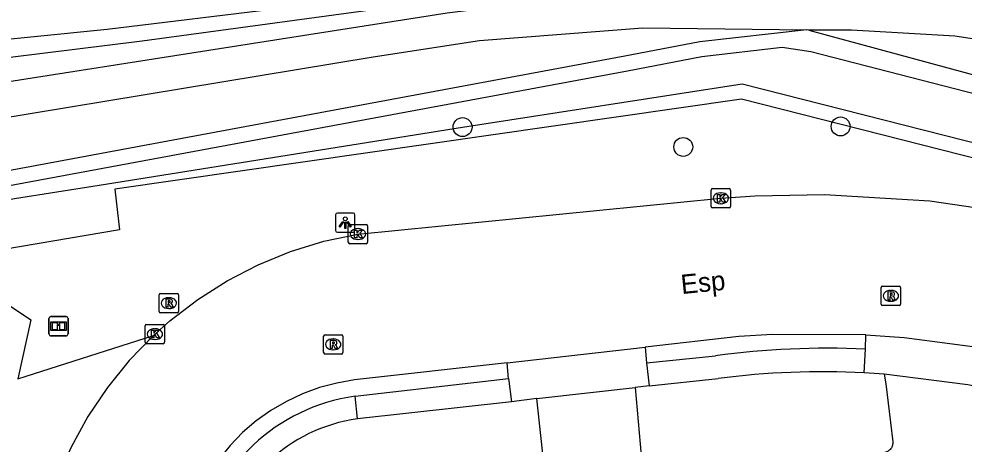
# Model space of a CAD drawing. Extents: x 161389 to 162585, y 388479 to 389761.
# Drawn here: x 162401.19 to 162450.14, y 389087.1 to 389109.12 of the extents above; entities that cross this region are included whole.
import ezdxf

# ---------------------------------------------------------------- set-up
doc = ezdxf.new("R2010")
doc.units = 0
for name, color, linetype in [('IMGEO_Boom', 7, 'Continuous'), ('IMGEO_Grasland_overig', 7, 'Continuous'), ('IMGEO_Groenvoorziening', 7, 'Continuous'), ('IMGEO_Informatiebord', 7, 'Continuous'), ('IMGEO_Kolk', 7, 'Continuous'), ('IMGEO_Lichtpunt', 7, 'Continuous'), ('IMGEO_Openbare_ruimte_label', 7, 'Continuous'), ('IMGEO_Rijbaan_lokaal_gesloten', 7, 'Continuous'), ('IMGEO_Rijbaan_lokaal_open', 7, 'Continuous'), ('IMGEO_Rioolput', 7, 'Continuous'), ('IMGEO_Voetpad_open', 7, 'Continuous'), ('IMGEO_Waterloop', 7, 'Continuous')]:
    doc.layers.add(name, color=color, linetype=linetype)

msp = doc.modelspace()

# ---------------------------------------------------------------- linework, layer by layer
at = {"layer": 'IMGEO_Boom'}
for centre in [(162424.166, 389103.514), (162443.743, 389103.548), (162435.594, 389102.487)]:
    msp.add_circle(centre, 0.489, dxfattribs=at)
at = {"layer": 'IMGEO_Grasland_overig'}
for points in [[(162443.128, 389111.815), (162441.869, 389111.714), (162423.37, 389109.414), (162387.435, 389103.792), (162386.449, 389103.86), (162385.337, 389104.032), (162384.246, 389104.303), (162383.182, 389104.67), (162382.156, 389105.13), (162381.175, 389105.68), (162380.247, 389106.316), (162379.38, 389107.032), (162377.829, 389109.083), (162376.361, 389111.024), (162369.698, 389125.495), (162363.721, 389145.826)], [(162345.171, 389069.022), (162346.529, 389070.241), (162347.773, 389071.576), (162348.632, 389072.657), (162357.656, 389083.031), (162363.851, 389089.234), (162366.896, 389092.076), (162370.937, 389095.277), (162372.4, 389096.154), (162374.82, 389097.375), (162377.339, 389098.374), (162379.935, 389099.397), (162385.624, 389101.218), (162387.811, 389101.86), (162390.049, 389102.288), (162419.529, 389107.157), (162425.043, 389108), (162433.502, 389108.658), (162441.985, 389108.557)], [(162442.099, 389108.529), (162441.985, 389108.557)], [(162490.431, 389095.003), (162489.427, 389095.363), (162466.901, 389103.815), (162460.173, 389106.152), (162454.96, 389107.42), (162449.656, 389108.217), (162444.301, 389108.537), (162442.099, 389108.529)]]:
    msp.add_lwpolyline(points, dxfattribs=at)
at = {"layer": 'IMGEO_Groenvoorziening'}
for points in [[(162378.38, 389110.682), (162379.528, 389110.312), (162380.637, 389109.275), (162382.947, 389107.385), (162384.59, 389106.646), (162386.048, 389106.318), (162393.071, 389106.318), (162399.046, 389106.934), (162407.567, 389107.981), (162426.033, 389110.496), (162442.252, 389112.986)], [(162441.985, 389108.557), (162436.446, 389107.928), (162432.566, 389107.183), (162394.86, 389100.187), (162377.318, 389096.648)], [(162442.099, 389108.529), (162463.695, 389102.686), (162488.778, 389092.794), (162488.169, 389091.372), (162487.431, 389089.647), (162462.452, 389098.908), (162438.603, 389104.956), (162406.149, 389100.295), (162406.403, 389098.189), (162400.404, 389097.175)], [(162345.423, 389058.454), (162354.094, 389069), (162374.638, 389088.034), (162399.442, 389095.107), (162401.799, 389093.537), (162401.128, 389090.478), (162408.163, 389092.728)]]:
    msp.add_lwpolyline(points, dxfattribs=at)
at = {"layer": 'IMGEO_Informatiebord'}
for p, q in [((162402.843, 389093.704), (162403.633, 389093.704)), ((162403.633, 389093.704), (162402.843, 389093.704)), ((162402.743, 389092.804), (162402.743, 389093.604)), ((162402.743, 389093.604), (162402.743, 389092.804)), ((162403.733, 389093.604), (162403.733, 389092.804)), ((162403.733, 389092.804), (162403.733, 389093.604)), ((162403.633, 389092.704), (162402.843, 389092.704)), ((162402.843, 389092.704), (162403.633, 389092.704))]:
    msp.add_line(p, q, dxfattribs=at)
for points in [[(162402.844, 389093.436), (162403.632, 389093.436), (162403.632, 389092.972), (162402.844, 389092.972), (162402.844, 389093.436)], [(162402.909, 389093.371), (162402.909, 389093.037), (162403.184, 389093.037), (162403.185, 389093.25), (162403.289, 389093.251), (162403.29, 389093.037), (162403.567, 389093.037), (162403.567, 389093.371), (162403.291, 389093.371), (162403.291, 389093.291), (162403.185, 389093.291), (162403.185, 389093.371), (162402.909, 389093.371)]]:
    msp.add_lwpolyline(points, dxfattribs=at)
for centre, start, end in [((162402.843, 389093.604), 90, 180), ((162402.843, 389093.604), 90, 180), ((162403.633, 389093.604), 0, 90), ((162403.633, 389093.604), 360, 90), ((162402.843, 389092.804), 180, 270), ((162402.843, 389092.804), 180, 270), ((162403.633, 389092.804), 270, 0), ((162403.633, 389092.804), 270, 0)]:
    msp.add_arc(centre, 0.1, start, end, dxfattribs=at)
at = {"layer": 'IMGEO_Kolk'}
for p, q in [((162437.039, 389099.401), (162437.039, 389100.253)), ((162437.114, 389100.327), (162437.966, 389100.327)), ((162437.527, 389100.107), (162437.552, 389100.107)), ((162438.04, 389100.253), (162438.04, 389099.401)), ((162437.55, 389099.547), (162437.525, 389099.547)), ((162437.966, 389099.327), (162437.114, 389099.327)), ((162418.246, 389097.55), (162418.246, 389098.402)), ((162418.321, 389098.476), (162419.173, 389098.476)), ((162418.734, 389098.256), (162418.759, 389098.256)), ((162419.247, 389098.402), (162419.247, 389097.55)), ((162418.757, 389097.696), (162418.732, 389097.696)), ((162419.173, 389097.476), (162418.321, 389097.476)), ((162407.731, 389092.369), (162407.731, 389093.221)), ((162407.806, 389093.295), (162408.658, 389093.295)), ((162408.732, 389093.221), (162408.732, 389092.369)), ((162408.219, 389093.075), (162408.244, 389093.075)), ((162408.658, 389092.295), (162407.806, 389092.295)), ((162408.242, 389092.515), (162408.217, 389092.515))]:
    msp.add_line(p, q, dxfattribs=at)
for points in [[(162437.039, 389099.401), (162437.039, 389100.253)], [(162437.114, 389100.327), (162437.966, 389100.327)], [(162437.36, 389100.027), (162437.483, 389100.027), (162437.483, 389099.876), (162437.613, 389100.027), (162437.777, 389100.027), (162437.631, 389099.876), (162437.784, 389099.627), (162437.632, 389099.627), (162437.547, 389099.791), (162437.483, 389099.724), (162437.483, 389099.627), (162437.36, 389099.627), (162437.36, 389100.027)], [(162438.04, 389100.253), (162438.04, 389099.401)], [(162437.966, 389099.327), (162437.114, 389099.327)], [(162418.246, 389097.55), (162418.246, 389098.402)], [(162418.321, 389098.476), (162419.173, 389098.476)], [(162418.567, 389098.176), (162418.69, 389098.176), (162418.69, 389098.025), (162418.82, 389098.176), (162418.984, 389098.176), (162418.838, 389098.025), (162418.991, 389097.776), (162418.839, 389097.776), (162418.754, 389097.94), (162418.69, 389097.873), (162418.69, 389097.776), (162418.567, 389097.776), (162418.567, 389098.176)], [(162419.247, 389098.402), (162419.247, 389097.55)], [(162419.173, 389097.476), (162418.321, 389097.476)], [(162407.731, 389092.369), (162407.731, 389093.221)], [(162407.806, 389093.295), (162408.658, 389093.295)], [(162408.732, 389093.221), (162408.732, 389092.369)], [(162408.052, 389092.995), (162408.175, 389092.995), (162408.175, 389092.844), (162408.305, 389092.995), (162408.469, 389092.995), (162408.323, 389092.844), (162408.476, 389092.595), (162408.324, 389092.595), (162408.239, 389092.759), (162408.175, 389092.692), (162408.175, 389092.595), (162408.052, 389092.595), (162408.052, 389092.995)], [(162408.658, 389092.295), (162407.806, 389092.295)]]:
    msp.add_lwpolyline(points, dxfattribs=at)
for centre, start, end in [((162437.116, 389100.251), 91.552, 178.448), ((162437.116, 389100.251), 91.552, 178.448), ((162437.964, 389100.251), 1.552, 88.448), ((162437.964, 389100.251), 1.552, 88.448), ((162437.116, 389099.403), 181.552, 268.448), ((162437.116, 389099.403), 181.552, 268.448), ((162437.964, 389099.403), 271.552, 358.448), ((162437.964, 389099.403), 271.552, 358.448), ((162418.323, 389098.4), 91.552, 178.448), ((162418.323, 389098.4), 91.552, 178.448), ((162419.171, 389098.4), 1.552, 88.448), ((162419.171, 389098.4), 1.552, 88.448), ((162418.323, 389097.552), 181.552, 268.448), ((162418.323, 389097.552), 181.552, 268.448), ((162419.171, 389097.552), 271.552, 358.448), ((162419.171, 389097.552), 271.552, 358.448), ((162407.808, 389093.219), 91.552, 178.448), ((162407.808, 389093.219), 91.552, 178.448), ((162408.656, 389093.219), 1.552, 88.448), ((162408.656, 389093.219), 1.552, 88.448), ((162407.808, 389092.371), 181.552, 268.448), ((162407.808, 389092.371), 181.552, 268.448), ((162408.656, 389092.371), 271.552, 358.448), ((162408.656, 389092.371), 271.552, 358.448)]:
    msp.add_arc(centre, 0.0765, start, end, dxfattribs=at)
for centre, major_axis, ratio, start_param, end_param in [((162437.526, 389099.827), (-0.387, 0.002), 0.722429, 4.712389, 7.853982), ((162437.551, 389099.827), (-0.39, 0.002), 0.717154, 1.570796, 4.712389), ((162418.733, 389097.976), (-0.387, 0.002), 0.722429, 4.712389, 7.853982), ((162418.758, 389097.976), (-0.39, 0.002), 0.717154, 1.570796, 4.712389), ((162408.218, 389092.795), (-0.387, 0.002), 0.722429, 4.712389, 7.853982), ((162408.243, 389092.795), (-0.39, 0.002), 0.717154, 1.570796, 4.712389)]:
    msp.add_ellipse(centre, major_axis=major_axis, ratio=ratio, start_param=start_param, end_param=end_param, dxfattribs=at)
at = {"layer": 'IMGEO_Lichtpunt'}
for p, q in [((162418.494, 389099.061), (162417.686, 389099.061)), ((162418.494, 389099.061), (162417.686, 389099.061)), ((162417.592, 389098.966), (162417.592, 389098.159)), ((162417.592, 389098.966), (162417.592, 389098.159)), ((162418.588, 389098.159), (162418.588, 389098.966)), ((162418.588, 389098.159), (162418.588, 389098.966)), ((162417.686, 389098.065), (162418.494, 389098.065)), ((162417.686, 389098.065), (162418.494, 389098.065))]:
    msp.add_line(p, q, dxfattribs=at)
for points in [[(162417.966, 389098.63), (162418.005, 389098.602), (162417.817, 389098.34), (162417.779, 389098.367), (162417.966, 389098.63)], [(162418.068, 389098.582), (162418.115, 389098.582), (162418.115, 389098.26), (162418.068, 389098.26), (162418.068, 389098.582)], [(162418.178, 389098.602), (162418.216, 389098.629), (162418.403, 389098.367), (162418.364, 389098.339), (162418.178, 389098.602)]]:
    msp.add_lwpolyline(points, dxfattribs=at)
msp.add_circle((162418.091, 389098.764), 0.0994, dxfattribs=at)
for centre, start, end in [((162417.686, 389098.966), 90, 180), ((162417.686, 389098.966), 90, 180), ((162418.494, 389098.966), 0, 90), ((162418.494, 389098.966), 0, 90), ((162417.686, 389098.159), 180, 270), ((162417.686, 389098.159), 180, 270), ((162418.494, 389098.159), 270, 0), ((162418.494, 389098.159), 270, 360)]:
    msp.add_arc(centre, 0.0946, start, end, dxfattribs=at)
at = {"layer": 'IMGEO_Rijbaan_lokaal_gesloten'}
for points in [[(162408.163, 389092.728), (162409.014, 389093.488), (162410.447, 389094.589), (162411.972, 389095.559), (162413.578, 389096.388), (162415.251, 389097.071), (162416.979, 389097.601), (162418.747, 389097.975), (162437.54, 389099.827), (162439.314, 389099.957), (162442.907, 389100.015), (162448.362, 389099.697), (162453.766, 389098.894), (162459.077, 389097.611), (162460.246, 389097.272), (162482.168, 389090.274), (162483.376, 389089.905), (162484.038, 389089.669), (162485.345, 389089.101), (162486.597, 389088.419), (162487.262, 389087.975)], [(162408.163, 389092.728), (162406.907, 389091.431), (162405.772, 389090.027), (162404.767, 389088.528), (162403.9, 389086.945), (162403.178, 389085.29), (162402.792, 389084.192), (162400.663, 389074.932), (162399.481, 389069.789)], [(162445.048, 389092.758), (162440.216, 389092.768), (162438.466, 389092.665), (162433.619, 389092.118)], [(162445.048, 389092.758), (162447.033, 389092.622), (162451.762, 389091.995), (162456.415, 389090.949), (162457.376, 389090.643)], [(162426.478, 389091.313), (162433.619, 389092.118)], [(162426.478, 389091.313), (162418.563, 389090.42), (162417.648, 389090.261), (162416.751, 389090.021), (162415.879, 389089.701), (162415.039, 389089.305), (162414.238, 389088.836), (162413.482, 389088.297), (162412.777, 389087.692), (162412.129, 389087.027), (162411.543, 389086.307), (162411.024, 389085.537), (162410.575, 389084.724), (162410.201, 389083.874), (162409.904, 389082.994), (162409.78, 389082.521), (162407.598, 389072.984)]]:
    msp.add_lwpolyline(points, dxfattribs=at)
at = {"layer": 'IMGEO_Rijbaan_lokaal_open'}
for points in [[(162446.006, 389090.713), (162446.086, 389090.21), (162446.445, 389087.22), (162446.447, 389087.174), (162446.444, 389087.126), (162446.438, 389087.079), (162446.427, 389087.033), (162446.412, 389086.988), (162446.393, 389086.945), (162446.37, 389086.903), (162446.344, 389086.863), (162446.314, 389086.826), (162446.281, 389086.792), (162446.245, 389086.761), (162446.207, 389086.733), (162446.166, 389086.709), (162446.123, 389086.689), (162446.079, 389086.672), (162446.033, 389086.659), (162445.986, 389086.651), (162445.239, 389086.59)], [(162455.744, 389089.055), (162450.339, 389090.173), (162446.006, 389090.713)], [(162428.004, 389089.451), (162433.112, 389090.025)], [(162433.112, 389090.025), (162433.461, 389085.928)], [(162428.451, 389085.477), (162428.004, 389089.451)]]:
    msp.add_lwpolyline(points, dxfattribs=at)
at = {"layer": 'IMGEO_Rioolput'}
for p, q in [((162445.845, 389094.349), (162445.845, 389095.201)), ((162445.92, 389095.275), (162446.772, 389095.275)), ((162446.846, 389095.201), (162446.846, 389094.349)), ((162408.453, 389093.972), (162408.453, 389094.824)), ((162408.528, 389094.898), (162409.38, 389094.898)), ((162408.941, 389094.678), (162408.966, 389094.678)), ((162409.454, 389094.824), (162409.454, 389093.972)), ((162446.333, 389095.055), (162446.358, 389095.055)), ((162408.964, 389094.118), (162408.939, 389094.118)), ((162446.772, 389094.275), (162445.92, 389094.275)), ((162446.356, 389094.495), (162446.331, 389094.495)), ((162409.38, 389093.898), (162408.528, 389093.898)), ((162416.967, 389091.837), (162416.967, 389092.689)), ((162417.042, 389092.763), (162417.894, 389092.763)), ((162417.968, 389092.689), (162417.968, 389091.837)), ((162417.455, 389092.543), (162417.48, 389092.543)), ((162417.894, 389091.763), (162417.042, 389091.763)), ((162417.478, 389091.983), (162417.453, 389091.983))]:
    msp.add_line(p, q, dxfattribs=at)
for points in [[(162445.845, 389094.349), (162445.845, 389095.201)], [(162445.92, 389095.275), (162446.772, 389095.275)], [(162446.846, 389095.201), (162446.846, 389094.349)], [(162408.453, 389093.972), (162408.453, 389094.824)], [(162408.528, 389094.898), (162409.38, 389094.898)], [(162409.454, 389094.824), (162409.454, 389093.972)], [(162446.434, 389094.973), (162446.182, 389094.975), (162446.182, 389094.575)], [(162446.182, 389094.575), (162446.306, 389094.575), (162446.306, 389094.737), (162446.317, 389094.737)], [(162446.36, 389094.894), (162446.306, 389094.894), (162446.306, 389094.813)], [(162446.306, 389094.813), (162446.358, 389094.813)], [(162446.364, 389094.708), (162446.435, 389094.575), (162446.575, 389094.575), (162446.51, 389094.701)], [(162409.042, 389094.596), (162408.79, 389094.598), (162408.79, 389094.198)], [(162408.79, 389094.198), (162408.914, 389094.198), (162408.914, 389094.36), (162408.925, 389094.36)], [(162408.968, 389094.517), (162408.914, 389094.517), (162408.914, 389094.436)], [(162408.914, 389094.436), (162408.966, 389094.436)], [(162408.972, 389094.331), (162409.043, 389094.198), (162409.183, 389094.198), (162409.118, 389094.324)], [(162446.772, 389094.275), (162445.92, 389094.275)], [(162409.38, 389093.898), (162408.528, 389093.898)], [(162416.967, 389091.837), (162416.967, 389092.689)], [(162417.042, 389092.763), (162417.894, 389092.763)], [(162417.968, 389092.689), (162417.968, 389091.837)], [(162417.556, 389092.461), (162417.304, 389092.463), (162417.304, 389092.063)], [(162417.304, 389092.063), (162417.428, 389092.063), (162417.428, 389092.225), (162417.439, 389092.225)], [(162417.482, 389092.382), (162417.428, 389092.382), (162417.428, 389092.301)], [(162417.428, 389092.301), (162417.48, 389092.301)], [(162417.486, 389092.196), (162417.557, 389092.063), (162417.697, 389092.063), (162417.632, 389092.189)], [(162417.894, 389091.763), (162417.042, 389091.763)]]:
    msp.add_lwpolyline(points, dxfattribs=at)
for centre, radius, start, end in [((162445.922, 389095.199), 0.0765, 91.552, 178.448), ((162445.922, 389095.199), 0.0765, 91.552, 178.448), ((162446.77, 389095.199), 0.0765, 1.552, 88.448), ((162446.77, 389095.199), 0.0765, 1.552, 88.448), ((162408.53, 389094.822), 0.0765, 91.552, 178.448), ((162408.53, 389094.822), 0.0765, 91.552, 178.448), ((162409.378, 389094.822), 0.0765, 1.552, 88.448), ((162409.378, 389094.822), 0.0765, 1.552, 88.448), ((162446.316, 389094.684), 0.0533, 26.0293, 88.6989), ((162446.342, 389095.002), 0.19, 274.7715, 282.9687), ((162446.366, 389094.798), 0.0964, 77.0061, 93.1865), ((162446.38, 389094.855), 0.0378, 276.6634, 79.6772), ((162446.433, 389094.863), 0.109, 350.3612, 89.416), ((162446.431, 389094.863), 0.112, 277.5842, 350.9817), ((162446.415, 389094.648), 0.108, 29.5134, 73.7905), ((162408.924, 389094.307), 0.0533, 26.0293, 88.6989), ((162408.95, 389094.625), 0.19, 274.7715, 282.9687), ((162408.974, 389094.421), 0.0964, 77.0061, 93.1865), ((162408.988, 389094.478), 0.0378, 276.6634, 79.6772), ((162409.041, 389094.486), 0.109, 350.3612, 89.416), ((162409.039, 389094.486), 0.112, 277.5842, 350.9817), ((162409.023, 389094.271), 0.108, 29.5134, 73.7905), ((162445.922, 389094.351), 0.0765, 181.552, 268.448), ((162445.922, 389094.351), 0.0765, 181.552, 268.448), ((162446.77, 389094.351), 0.0765, 271.552, 358.448), ((162446.77, 389094.351), 0.0765, 271.552, 358.448), ((162408.53, 389093.974), 0.0765, 181.552, 268.448), ((162408.53, 389093.974), 0.0765, 181.552, 268.448), ((162409.378, 389093.974), 0.0765, 271.552, 358.448), ((162409.378, 389093.974), 0.0765, 271.552, 358.448), ((162417.044, 389092.687), 0.0765, 91.552, 178.448), ((162417.044, 389092.687), 0.0765, 91.552, 178.448), ((162417.892, 389092.687), 0.0765, 1.552, 88.448), ((162417.892, 389092.687), 0.0765, 1.552, 88.448), ((162417.438, 389092.172), 0.0533, 26.0293, 88.6989), ((162417.464, 389092.49), 0.19, 274.7715, 282.9687), ((162417.488, 389092.286), 0.0964, 77.0061, 93.1865), ((162417.502, 389092.343), 0.0378, 276.6634, 79.6772), ((162417.555, 389092.351), 0.109, 350.3612, 89.416), ((162417.553, 389092.351), 0.112, 277.5842, 350.9817), ((162417.537, 389092.136), 0.108, 29.5134, 73.7905), ((162417.044, 389091.839), 0.0765, 181.552, 268.448), ((162417.044, 389091.839), 0.0765, 181.552, 268.448), ((162417.892, 389091.839), 0.0765, 271.552, 358.448), ((162417.892, 389091.839), 0.0765, 271.552, 358.448)]:
    msp.add_arc(centre, radius, start, end, dxfattribs=at)
for centre, major_axis, ratio, start_param, end_param in [((162408.94, 389094.398), (-0.387, 0.002), 0.722429, 4.712389, 7.853982), ((162408.965, 389094.398), (-0.39, 0.002), 0.717154, 1.570796, 4.712389), ((162446.332, 389094.775), (-0.387, 0.002), 0.722429, 4.712389, 7.853982), ((162446.357, 389094.775), (-0.39, 0.002), 0.717154, 1.570796, 4.712389), ((162417.454, 389092.263), (-0.387, 0.002), 0.722429, 4.712389, 7.853982), ((162417.479, 389092.263), (-0.39, 0.002), 0.717154, 1.570796, 4.712389)]:
    msp.add_ellipse(centre, major_axis=major_axis, ratio=ratio, start_param=start_param, end_param=end_param, dxfattribs=at)
at = {"layer": 'IMGEO_Voetpad_open'}
for points in [[(162445.029, 389092.015), (162445.048, 389092.758)], [(162433.619, 389092.118), (162433.69, 389091.302)], [(162444.97, 389090.788), (162445.029, 389092.015)], [(162426.547, 389090.495), (162426.478, 389091.313)], [(162433.69, 389091.302), (162437.261, 389091.667)], [(162433.69, 389091.302), (162433.829, 389090.113)], [(162446.006, 389090.713), (162444.97, 389090.788)], [(162418.6, 389089.575), (162426.547, 389090.495)], [(162426.547, 389090.495), (162426.698, 389089.293)], [(162433.829, 389090.113), (162437.394, 389090.494)], [(162433.829, 389090.113), (162433.112, 389090.025)], [(162418.727, 389088.407), (162418.6, 389089.575)], [(162426.698, 389089.293), (162418.727, 389088.407)], [(162428.004, 389089.451), (162426.698, 389089.293)]]:
    msp.add_lwpolyline(points, dxfattribs=at)
for centre, radius, start, end in [((162443.039, 389049.555), 42.506, 87.3171, 97.8131), ((162442.836, 389048.025), 42.817, 87.1429, 97.3018), ((162419.935, 389080.009), 9.659, 97.944, 168.5041), ((162419.88, 389080.12), 8.367, 97.9226, 169.4164)]:
    msp.add_arc(centre, radius, start, end, dxfattribs=at)
at = {"layer": 'IMGEO_Waterloop'}
for points in [[(162461.5, 389118.638), (162461.715, 389117.19), (162445.144, 389114.275), (162431.746, 389111.934), (162423.948, 389110.794), (162405.761, 389108.576), (162393.877, 389107.375), (162391.454, 389107.211), (162388.998, 389107.246), (162385.114, 389107.724)], [(162486.958, 389092.675), (162463.45, 389101.946), (162442.207, 389107.406), (162440.715, 389107.629), (162436.563, 389107.158), (162432.71, 389106.418), (162395.008, 389099.423), (162394.401, 389099.278)], [(162347.36, 389067.365), (162347.462, 389067.423), (162348.025, 389067.712), (162371.925, 389093.029), (162374.412, 389094.498), (162377.586, 389095.388), (162389.587, 389097.707), (162400.959, 389099.822), (162405.34, 389100.503), (162424.166, 389103.514), (162438.645, 389105.748), (162462.684, 389099.652), (162486.213, 389090.928), (162486.356, 389090.894), (162486.503, 389090.864), (162486.565, 389090.853)]]:
    msp.add_lwpolyline(points, dxfattribs=at)

# ---------------------------------------------------------------- texts
at = {"layer": 'IMGEO_Openbare_ruimte_label'}
msp.add_text('Esp', height=1, rotation=5.6251, dxfattribs=at).set_placement((162435.517, 389094.864))

doc.saveas('drawing.dxf')
